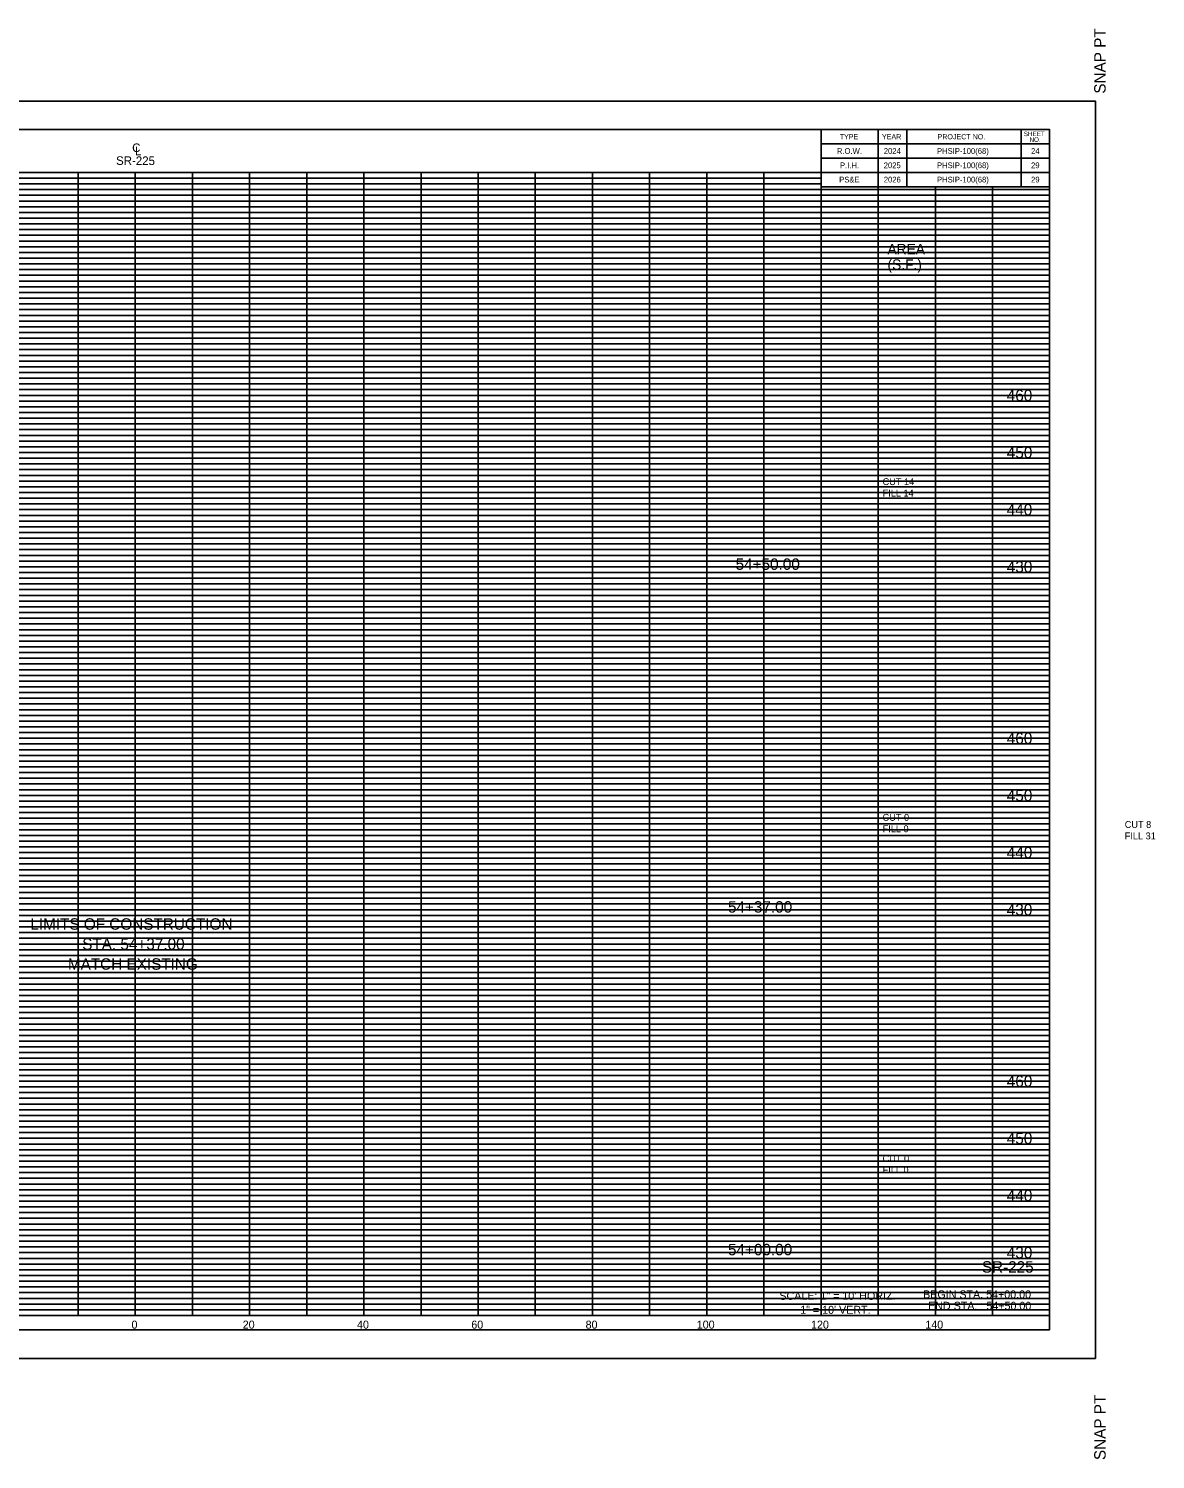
# Model space of a CAD drawing. Extents: x 967 to 1339, y 975 to 1507.
# Drawn here: x 1141.3 to 1338.5, y 974.8 to 1225.2 of the extents above; entities that cross this region are included whole.
import ezdxf

# ---------------------------------------------------------------- set-up
doc = ezdxf.new("R2010")
doc.units = 0
for name, color, linetype in [('Default', 7, 'Continuous'), ('DESIGN - DRAINAGE - Special Ditch Width Text', 7, 'Continuous'), ('DESIGN - SCRATCH - User 1', 7, 'Continuous'), ('DESIGN - SHEET - Corner Text', 7, 'Continuous'), ('DESIGN - SHEET - Light Grid', 7, 'Continuous'), ('DESIGN - SHEET - Linework', 7, 'Continuous'), ('DESIGN - SHEET - Plot Shape', 7, 'Continuous'), ('DESIGN - TYPICAL - Text', 7, 'Continuous')]:
    doc.layers.add(name, color=color, linetype=linetype)

msp = doc.modelspace()

# ---------------------------------------------------------------- linework, layer by layer
at = {"layer": 'DESIGN - SCRATCH - User 1'}
for p, q in [((1285, 1203.75), (1285, 1203.75)), ((1292.5, 1203.75), (1292.5, 1203.75)), ((1305, 1203.75), (1305, 1203.75)), ((1317.5, 1203.75), (1317.5, 1203.75)), ((1285, 1201.25), (1285, 1201.25)), ((1292.5, 1201.25), (1292.5, 1201.25)), ((1305, 1201.25), (1305, 1201.25)), ((1317.5, 1201.25), (1317.5, 1201.25))]:
    msp.add_line(p, q, dxfattribs=at)
at = {"layer": 'DESIGN - SHEET - Light Grid'}
for p, q in [((1000, 1199), (1280, 1199)), ((1000, 1198), (1280, 1198)), ((1000, 1197), (1320, 1197)), ((1000, 1196), (1320, 1196)), ((1000, 1195), (1320, 1195)), ((1000, 1194), (1320, 1194)), ((1000, 1193), (1320, 1193)), ((1000, 1192), (1320, 1192)), ((1000, 1191), (1320, 1191)), ((1000, 1189), (1320, 1189)), ((1000, 1188), (1320, 1188)), ((1000, 1187), (1320, 1187)), ((1000, 1186), (1320, 1186)), ((1000, 1185), (1320, 1185)), ((1000, 1184), (1320, 1184)), ((1000, 1183), (1320, 1183)), ((1000, 1182), (1320, 1182)), ((1000, 1181), (1320, 1181)), ((1000, 1179), (1320, 1179)), ((1000, 1178), (1320, 1178)), ((1000, 1177), (1320, 1177)), ((1000, 1176), (1320, 1176)), ((1000, 1175), (1320, 1175)), ((1000, 1174), (1320, 1174)), ((1000, 1173), (1320, 1173)), ((1000, 1172), (1320, 1172)), ((1000, 1171), (1320, 1171)), ((1000, 1169), (1320, 1169)), ((1000, 1168), (1320, 1168)), ((1000, 1167), (1320, 1167)), ((1000, 1166), (1320, 1166)), ((1000, 1165), (1320, 1165)), ((1000, 1164), (1320, 1164)), ((1000, 1163), (1320, 1163)), ((1000, 1162), (1320, 1162)), ((1000, 1161), (1320, 1161)), ((1000, 1159), (1320, 1159)), ((1000, 1158), (1320, 1158)), ((1000, 1157), (1320, 1157)), ((1000, 1156), (1320, 1156)), ((1000, 1155), (1320, 1155)), ((1000, 1154), (1320, 1154)), ((1000, 1153), (1320, 1153)), ((1000, 1152), (1320, 1152)), ((1000, 1151), (1320, 1151)), ((1000, 1149), (1320, 1149)), ((1000, 1148), (1320, 1148)), ((1000, 1147), (1320, 1147)), ((1000, 1146), (1320, 1146)), ((1000, 1145), (1320, 1145)), ((1000, 1144), (1320, 1144)), ((1000, 1143), (1320, 1143)), ((1000, 1142), (1320, 1142)), ((1000, 1141), (1320, 1141)), ((1000, 1139), (1320, 1139)), ((1000, 1138), (1320, 1138)), ((1000, 1137), (1320, 1137)), ((1000, 1136), (1320, 1136)), ((1000, 1135), (1320, 1135)), ((1000, 1134), (1320, 1134)), ((1000, 1133), (1320, 1133)), ((1000, 1132), (1320, 1132)), ((1000, 1131), (1320, 1131)), ((1000, 1129), (1320, 1129)), ((1000, 1128), (1320, 1128)), ((1000, 1127), (1320, 1127)), ((1000, 1126), (1320, 1126)), ((1000, 1125), (1320, 1125)), ((1000, 1124), (1320, 1124)), ((1000, 1123), (1320, 1123)), ((1000, 1122), (1320, 1122)), ((1000, 1121), (1320, 1121)), ((1000, 1119), (1320, 1119)), ((1000, 1118), (1320, 1118)), ((1000, 1117), (1320, 1117)), ((1000, 1116), (1320, 1116)), ((1000, 1115), (1320, 1115)), ((1000, 1114), (1320, 1114)), ((1000, 1113), (1320, 1113)), ((1000, 1112), (1320, 1112)), ((1000, 1111), (1320, 1111)), ((1000, 1109), (1320, 1109)), ((1000, 1108), (1320, 1108)), ((1000, 1107), (1320, 1107)), ((1000, 1106), (1320, 1106)), ((1000, 1105), (1320, 1105)), ((1000, 1104), (1320, 1104)), ((1000, 1103), (1320, 1103)), ((1000, 1102), (1320, 1102)), ((1000, 1101), (1320, 1101)), ((1000, 1099), (1320, 1099)), ((1000, 1098), (1320, 1098)), ((1000, 1097), (1320, 1097)), ((1000, 1096), (1320, 1096)), ((1000, 1095), (1320, 1095)), ((1000, 1094), (1320, 1094)), ((1000, 1093), (1320, 1093)), ((1000, 1092), (1320, 1092)), ((1000, 1091), (1320, 1091)), ((1000, 1089), (1320, 1089)), ((1000, 1088), (1320, 1088)), ((1000, 1087), (1320, 1087)), ((1000, 1086), (1320, 1086)), ((1000, 1085), (1320, 1085)), ((1000, 1084), (1320, 1084)), ((1000, 1083), (1320, 1083)), ((1000, 1082), (1320, 1082)), ((1000, 1081), (1320, 1081)), ((1000, 1079), (1320, 1079)), ((1000, 1078), (1320, 1078)), ((1000, 1077), (1320, 1077)), ((1000, 1076), (1320, 1076)), ((1000, 1075), (1320, 1075)), ((1000, 1074), (1320, 1074)), ((1000, 1073), (1320, 1073)), ((1000, 1072), (1320, 1072)), ((1000, 1071), (1320, 1071)), ((1000, 1069), (1320, 1069)), ((1000, 1068), (1320, 1068)), ((1000, 1067), (1320, 1067)), ((1000, 1066), (1320, 1066)), ((1000, 1065), (1320, 1065)), ((1000, 1064), (1320, 1064)), ((1000, 1063), (1320, 1063)), ((1000, 1062), (1320, 1062)), ((1000, 1061), (1320, 1061)), ((1000, 1059), (1320, 1059)), ((1000, 1058), (1320, 1058)), ((1000, 1057), (1320, 1057)), ((1000, 1056), (1320, 1056)), ((1000, 1055), (1320, 1055)), ((1000, 1054), (1320, 1054)), ((1000, 1053), (1320, 1053)), ((1000, 1052), (1320, 1052)), ((1000, 1051), (1320, 1051)), ((1000, 1049), (1320, 1049)), ((1000, 1048), (1320, 1048)), ((1000, 1047), (1320, 1047)), ((1000, 1046), (1320, 1046)), ((1000, 1045), (1320, 1045)), ((1000, 1044), (1320, 1044)), ((1000, 1043), (1320, 1043)), ((1000, 1042), (1320, 1042)), ((1000, 1041), (1320, 1041)), ((1000, 1039), (1320, 1039)), ((1000, 1038), (1320, 1038)), ((1000, 1037), (1320, 1037)), ((1000, 1036), (1320, 1036)), ((1000, 1035), (1320, 1035)), ((1000, 1034), (1320, 1034)), ((1000, 1033), (1320, 1033)), ((1000, 1032), (1320, 1032)), ((1000, 1031), (1320, 1031)), ((1000, 1029), (1320, 1029)), ((1000, 1028), (1320, 1028)), ((1000, 1027), (1320, 1027)), ((1000, 1026), (1320, 1026)), ((1000, 1025), (1320, 1025)), ((1000, 1024), (1320, 1024)), ((1000, 1023), (1320, 1023)), ((1000, 1022), (1320, 1022)), ((1000, 1021), (1320, 1021)), ((1000, 1019), (1320, 1019)), ((1000, 1018), (1320, 1018)), ((1000, 1017), (1320, 1017)), ((1000, 1016), (1320, 1016)), ((1000, 1015), (1320, 1015)), ((1000, 1014), (1320, 1014)), ((1000, 1013), (1320, 1013)), ((1000, 1012), (1320, 1012)), ((1000, 1011), (1320, 1011)), ((1000, 1009), (1320, 1009)), ((1000, 1008), (1320, 1008)), ((1000, 1007), (1320, 1007)), ((1000, 1006), (1320, 1006)), ((1000, 1005), (1320, 1005)), ((1000, 1004), (1320, 1004)), ((1000, 1003), (1320, 1003)), ((1000, 1002), (1320, 1002)), ((1000, 1001), (1320, 1001))]:
    msp.add_line(p, q, dxfattribs=at)
at = {"layer": 'DESIGN - SHEET - Linework'}
for p, q in [((1320, 1207.5), (1280, 1207.5)), ((1280, 1200), (1280, 1207.5)), ((1290, 1200), (1290, 1207.5)), ((1295, 1197.5), (1295, 1207.5)), ((1315, 1197.5), (1315, 1207.5)), ((1320, 1200), (1320, 1207.5)), ((1320, 1205), (1280, 1205)), ((1320, 1202.5), (1280, 1202.5)), ((1000, 1200), (1320, 1200)), ((1150, 1000), (1150, 1200)), ((1160, 1000), (1160, 1200)), ((1170, 1000), (1170, 1200)), ((1180, 1000), (1180, 1200)), ((1190, 1000), (1190, 1200)), ((1200, 1000), (1200, 1200)), ((1210, 1000), (1210, 1200)), ((1220, 1000), (1220, 1200)), ((1230, 1000), (1230, 1200)), ((1240, 1000), (1240, 1200)), ((1250, 1000), (1250, 1200)), ((1260, 1000), (1260, 1200)), ((1270, 1000), (1270, 1200)), ((1280, 1000), (1280, 1200)), ((1290, 1000), (1290, 1200)), ((1320, 1197.5), (1280, 1197.5)), ((1300, 1000), (1300, 1197.5)), ((1310, 1000), (1310, 1197.5)), ((1000, 1190), (1320, 1190)), ((1000, 1180), (1320, 1180)), ((1000, 1170), (1320, 1170)), ((1000, 1160), (1320, 1160)), ((1000, 1150), (1320, 1150)), ((1000, 1140), (1320, 1140)), ((1000, 1130), (1320, 1130)), ((1000, 1120), (1320, 1120)), ((1000, 1110), (1320, 1110)), ((1000, 1100), (1320, 1100)), ((1000, 1090), (1320, 1090)), ((1000, 1080), (1320, 1080)), ((1000, 1070), (1320, 1070)), ((1000, 1060), (1320, 1060)), ((1000, 1050), (1320, 1050)), ((1000, 1040), (1320, 1040)), ((1000, 1030), (1320, 1030)), ((1000, 1020), (1320, 1020)), ((1000, 1010), (1320, 1010)), ((1000, 1000), (1320, 1000))]:
    msp.add_line(p, q, dxfattribs=at)
for points in [[(988, 1212.5), (1328, 1212.5), (1328, 992.5), (988, 992.5)], [(1000, 1207.5), (1320, 1207.5), (1320, 997.5), (1000, 997.5)]]:
    msp.add_lwpolyline(points, close=True, dxfattribs=at)
at = {"layer": 'DESIGN - SHEET - Plot Shape'}
msp.add_lwpolyline([(990, 1207.5), (1320, 1207.5), (1320, 997.5), (990, 997.5)], close=True, dxfattribs=at)

# ---------------------------------------------------------------- texts
at = {"layer": 'Default'}
for s, height, p in [('     460     ', 2, (1308.78, 1160)), ('     450     ', 2, (1308.79, 1150)), ('     440     ', 2, (1308.78, 1140)), ('     54+50.00     ', 2, (1261.34, 1130.47)), ('     430     ', 2, (1308.79, 1130)), ('     460     ', 2, (1308.79, 1100)), ('     450     ', 2, (1308.79, 1090)), ('     440     ', 2, (1308.79, 1080)), ('     54+37.00     ', 2, (1260, 1070.49)), ('     430     ', 2, (1308.79, 1070)), ('     460     ', 2, (1308.79, 1040)), ('     450     ', 2, (1308.79, 1030)), ('     440     ', 2, (1308.79, 1020)), ('     54+00.00     ', 2, (1260, 1010.53)), ('     430     ', 2, (1308.79, 1010)), ('     0     ', 1.4, (1156.74, 997.7)), ('     0     ', 1.4, (1156.74, 997.7)), ('     20     ', 1.4, (1176.2, 997.7)), ('     40     ', 1.4, (1196.2, 997.7)), ('     60     ', 1.4, (1216.2, 997.7)), ('     80     ', 1.4, (1236.2, 997.7)), ('     100     ', 1.4, (1255.65, 997.7)), ('     120     ', 1.4, (1275.65, 997.7)), ('     140     ', 1.4, (1295.65, 997.7))]:
    msp.add_text(s, height=height, dxfattribs=at).set_placement(p)
at = {"layer": 'DESIGN - DRAINAGE - Special Ditch Width Text'}
for s, p in [('C', (1159.45, 1203.57)), ('L', (1159.94, 1203.01)), ('SR-225', (1156.64, 1201.33))]:
    msp.add_text(s, height=1.5, rotation=359.6675, dxfattribs=at).set_placement(p)
at = {"layer": 'DESIGN - SHEET - Corner Text'}
for s, p in [('  SNAP PT', (1329.8, 1212.3)), ('SNAP PT  ', (1329.8, 974.7))]:
    msp.add_text(s, height=2, rotation=90, dxfattribs=at).set_placement(p)
for s, height, p in [('R.O.W.', 1, (1282.77, 1203.25)), ('2024', 1, (1290.98, 1203.25)), ('PHSIP-100(68)', 1, (1300.29, 1203.25)), ('24', 1, (1316.76, 1203.25)), ('P.I.H.', 1, (1283.31, 1200.75)), ('2025', 1, (1290.97, 1200.75)), ('PHSIP-100(68)', 1, (1300.29, 1200.75)), ('29', 1, (1316.75, 1200.75)), ('PS&E', 1, (1283.17, 1198.25)), ('2026', 1, (1290.98, 1198.25)), ('PHSIP-100(68)', 1, (1300.29, 1198.25)), ('29', 1, (1316.75, 1198.25)), ('SR-225', 2, (1308.14, 1007.5)), ('SCALE: 1" = 10\' HORIZ.', 1.4, (1272.71, 1002.74)), ('BEGIN STA. 54+00.00', 1.4, (1297.86, 1003)), ('       1" = 10\' VERT.   ', 1.4, (1272.71, 1000.29)), ('END STA.   54+50.00', 1.4, (1298.73, 1001))]:
    msp.add_text(s, height=height, dxfattribs=at).set_placement(p)
at = {"layer": 'DESIGN - SHEET - Light Grid'}
for s, height, p in [('TYPE', 0.9, (1283.26, 1205.8)), ('YEAR', 0.9, (1290.66, 1205.8)), ('PROJECT NO.', 0.9, (1300.38, 1205.8)), ('SHEET', 0.8, (1315.47, 1206.35)), ('NO.', 0.8, (1316.47, 1205.35))]:
    msp.add_text(s, height=height, dxfattribs=at).set_placement(p)
at = {"layer": 'DESIGN - TYPICAL - Text'}
for s, height, p in [('AREA ', 1.8, (1291.63, 1185.69)), ('(S.F.)', 1.8, (1291.63, 1182.99)), ('CUT 14', 1.2, (1290.77, 1145.3)), ('FILL 14', 1.2, (1290.77, 1143.3)), ('CUT 0', 1.2, (1290.77, 1086.56)), ('CUT 8', 1.2, (1333.14, 1085.31)), ('FILL 0', 1.2, (1290.77, 1084.56)), ('FILL 31', 1.2, (1333.14, 1083.31)), ('LIMITS OF CONSTRUCTION', 2, (1141.64, 1067.5)), ('STA. 54+37.00', 2, (1150.71, 1064)), ('MATCH EXISTING', 2, (1148.21, 1060.5)), ('CUT 0', 1.2, (1290.77, 1026.88)), ('FILL 0', 1.2, (1290.77, 1024.88))]:
    msp.add_text(s, height=height, dxfattribs=at).set_placement(p)

doc.saveas('drawing.dxf')
